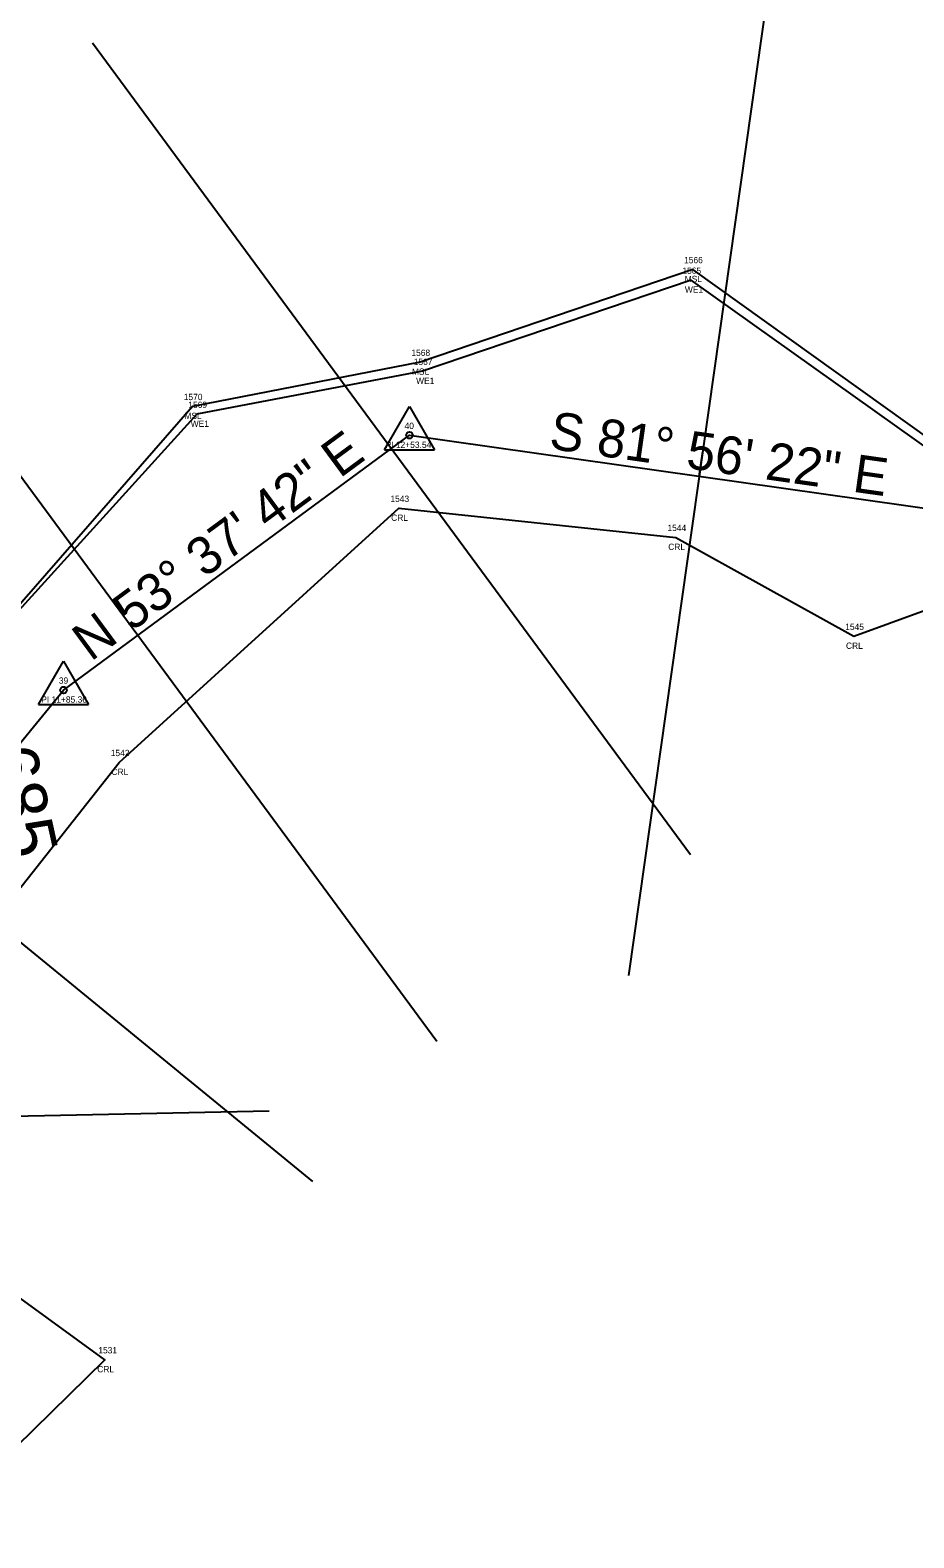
# Model space of a CAD drawing. Extents: x 2522090 to 2524658, y 882711 to 887512.
# Drawn here: x 2523878.4 to 2524018.6, y 885126.7 to 885366 of the extents above; entities that cross this region are included whole.
import ezdxf

# ---------------------------------------------------------------- set-up
doc = ezdxf.new("R2010")
doc.units = 0
for name, color, linetype in [('RD_EX_H2O', 7, 'Continuous'), ('RD_EX_H2O_txCode', 7, 'Continuous'), ('RD_EX_Misc', 7, 'Continuous'), ('RD_EX_Misc_txCode', 7, 'Continuous'), ('RD_HC_Cl', 7, 'Continuous'), ('RD_HC_Data', 7, 'Continuous'), ('RD_HC_Data_Tic', 7, 'Continuous'), ('RD_HC_TX_Sta50', 7, 'Continuous'), ('RD_HC_txCode', 7, 'Continuous'), ('RD_PD_PatLn6', 7, 'Continuous'), ('RD_SMD_Locator', 7, 'Continuous')]:
    doc.layers.add(name, color=color, linetype=linetype)

msp = doc.modelspace()

# ---------------------------------------------------------------- linework, layer by layer
at = {"layer": 'RD_EX_H2O'}
for points in [[(2524064.86, 885165.15), (2524036.37, 885213.78), (2524057.22, 885252.72), (2524031.95, 885291.63), (2523983.25, 885326.3), (2523940.61, 885311.83), (2523904.84, 885305.01), (2523874.98, 885272.1), (2523850.32, 885280.24), (2523830.66, 885258.8), (2523826.93, 885206.61)], [(2523582.82, 884766.34), (2523598.11, 884856.98), (2523627.59, 884901.75), (2523623.76, 884928.28), (2523586.58, 884955.43), (2523600.94, 884974.12), (2523633.05, 884997.68), (2523679.17, 885037.05), (2523744.72, 885076.89), (2523769.38, 885099), (2523825.47, 885108.66), (2523825.47, 885108.66), (2523845.24, 885110.83), (2523890.25, 885154.93), (2523858.43, 885178.04), (2523850.81, 885196.93), (2523892.51, 885249.74), (2523936.89, 885290.09), (2523980.86, 885285.47), (2524009.06, 885269.77), (2524037.39, 885280.09)]]:
    msp.add_lwpolyline(points, dxfattribs=at)
at = {"layer": 'RD_EX_Misc'}
msp.add_lwpolyline([(2524066.31, 885165.35), (2524037.3, 885214.15), (2524057.95, 885253.07), (2524039.52, 885283.17), (2524032.92, 885292.57), (2523983.53, 885327.98), (2523940.24, 885313.27), (2523904.13, 885306.25), (2523874.86, 885272.67), (2523849.96, 885282.51), (2523827.65, 885261.93), (2523821.38, 885209.28)], dxfattribs=at)
at = {"layer": 'RD_HC_Cl'}
for p, q in [((2523883.66, 885261.23), (2523938.56, 885301.67)), ((2523938.56, 885301.67), (2524036.25, 885287.83)), ((2523836.11, 885203.1), (2523883.66, 885261.23))]:
    msp.add_line(p, q, dxfattribs=at)
at = {"layer": 'RD_HC_Data'}
for p, q in [((2523934.59, 885299.37), (2523938.56, 885306.25)), ((2523938.56, 885306.25), (2523942.53, 885299.37)), ((2523934.59, 885299.37), (2523942.53, 885299.37)), ((2523879.69, 885258.94), (2523883.66, 885265.82)), ((2523883.66, 885265.82), (2523887.63, 885258.94)), ((2523879.69, 885258.94), (2523887.63, 885258.94))]:
    msp.add_line(p, q, dxfattribs=at)
for centre in [(2523938.56, 885301.67), (2523883.66, 885261.23)]:
    msp.add_circle(centre, 0.529, dxfattribs=at)
at = {"layer": 'RD_HC_Data_Tic'}
for p, q in [((2523984.56, 885295.15), (2523985.12, 885299.11)), ((2523895.45, 885269.91), (2523893.08, 885273.13))]:
    msp.add_line(p, q, dxfattribs=at)
at = {"layer": 'RD_PD_PatLn6'}
for p, q in [((2523995.77, 885374.36), (2523973.34, 885215.94)), ((2523888.27, 885363.98), (2523983.15, 885235.15)), ((2523848.01, 885334.33), (2523942.89, 885205.5)), ((2523799.35, 885284.52), (2523923.19, 885183.21)), ((2523756.32, 885191.28), (2523916.29, 885194.41))]:
    msp.add_line(p, q, dxfattribs=at)
at = {"layer": 'RD_SMD_Locator'}
for centre in [(2523983.25, 885326.3), (2523983.53, 885327.98), (2523940.24, 885313.27), (2523940.61, 885311.83), (2523904.13, 885306.25), (2523904.84, 885305.01), (2523938.56, 885301.67), (2523936.89, 885290.09), (2523980.86, 885285.47), (2524009.06, 885269.77), (2523883.66, 885261.23), (2523892.51, 885249.74), (2523890.25, 885154.93)]:
    msp.add_circle(centre, 0.001, dxfattribs=at)

# ---------------------------------------------------------------- texts
at = {"layer": 'RD_EX_H2O_txCode'}
for s, p in [('1565', (2523981.88, 885327.3)), ('WE1', (2523982.27, 885324.3)), ('1567', (2523939.24, 885312.83)), ('WE1', (2523939.62, 885309.83)), ('1569', (2523903.47, 885306.01)), ('WE1', (2523903.85, 885303.01)), ('1543', (2523935.54, 885291.09)), ('CRL', (2523935.66, 885288.09)), ('1544', (2523979.51, 885286.47)), ('CRL', (2523979.63, 885283.47)), ('1545', (2524007.71, 885270.77)), ('CRL', (2524007.83, 885267.77)), ('1542', (2523891.16, 885250.74)), ('CRL', (2523891.28, 885247.74)), ('1531', (2523889.19, 885155.93)), ('CRL', (2523889.02, 885152.93))]:
    msp.add_text(s, height=1, dxfattribs=at).set_placement(p)
at = {"layer": 'RD_EX_Misc_txCode'}
for s, p in [('1566', (2523982.14, 885328.98)), ('MSL', (2523982.24, 885325.98)), ('1568', (2523938.87, 885314.27)), ('MSL', (2523938.95, 885311.27)), ('1570', (2523902.75, 885307.25)), ('MSL', (2523902.84, 885304.25))]:
    msp.add_text(s, height=1, dxfattribs=at).set_placement(p)
at = {"layer": 'RD_HC_Data'}
for s, rotation, p in [('S 81%%d 56\' 22" E', 351.9395, (2523960.57, 885299.56)), ('N 53%%d 37\' 42" E', 36.3717, (2523887.99, 885265.66))]:
    msp.add_text(s, height=6, rotation=rotation, dxfattribs=at).set_placement(p)
at = {"layer": 'RD_HC_TX_Sta50'}
msp.add_text('685', height=8, rotation=282.4185, dxfattribs=at).set_placement((2523871.26, 885251.48))
at = {"layer": 'RD_HC_txCode'}
for s, p in [('40', (2523937.79, 885302.67)), ('PI 12+53.54', (2523934.78, 885299.67)), ('39', (2523882.93, 885262.23)), ('PI 11+85.36', (2523880.14, 885259.23))]:
    msp.add_text(s, height=1, dxfattribs=at).set_placement(p)

doc.saveas('drawing.dxf')
